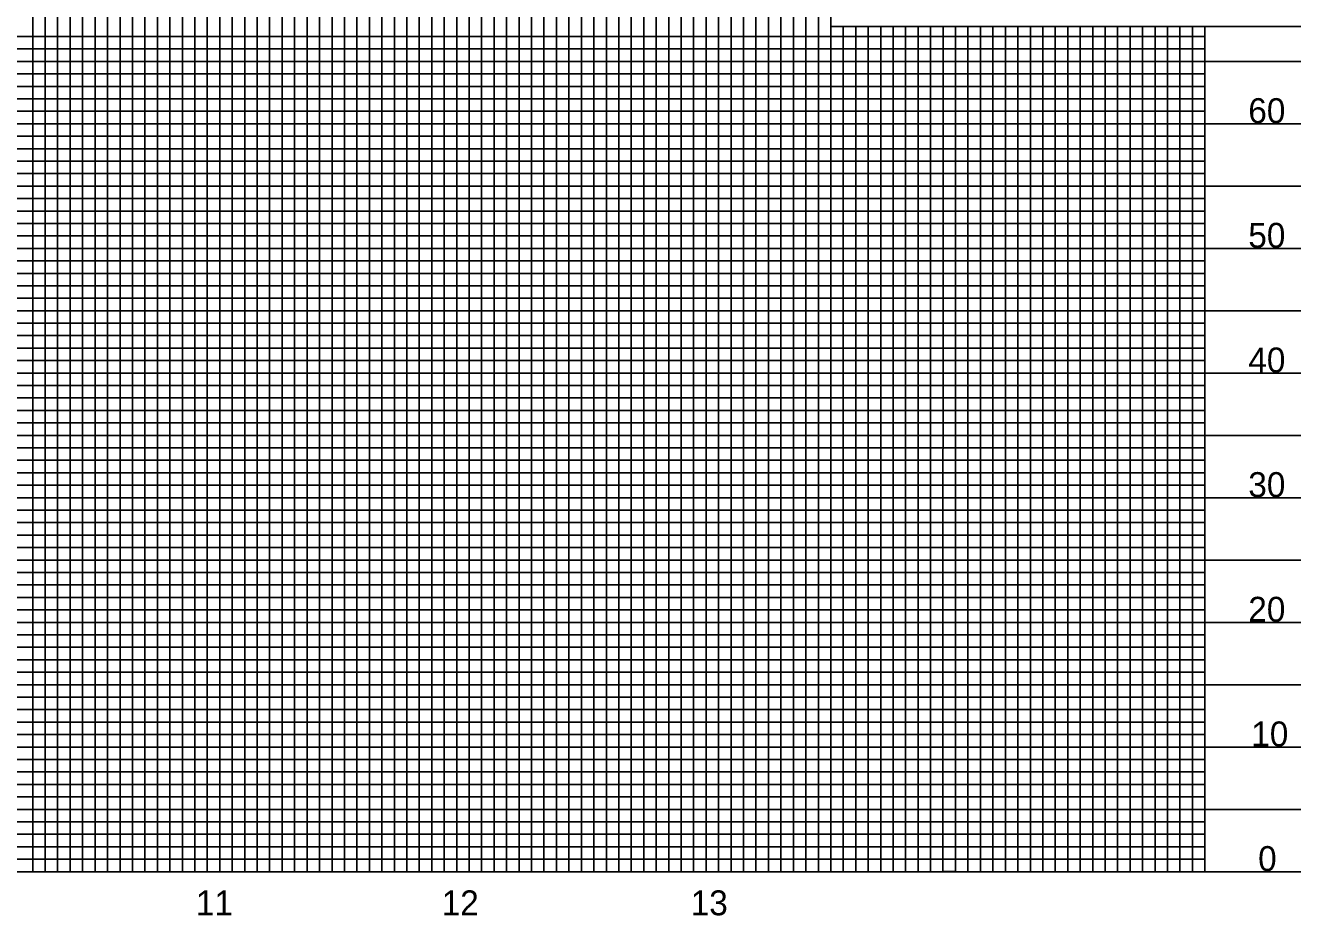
# Model space of a CAD drawing. Extents: x 2186391 to 2188300, y 74582 to 75682.
# Drawn here: x 2187535 to 2188043, y 75140 to 75497 of the extents above; entities that cross this region are included whole.
import ezdxf

# ---------------------------------------------------------------- set-up
doc = ezdxf.new("R2010")
doc.units = 0
for name, color, linetype in [('Old_Level_1', 7, 'Continuous'), ('Old_Level_11', 7, 'Continuous'), ('Old_Level_2', 7, 'Continuous'), ('Old_Level_3', 7, 'Continuous'), ('Sheet Cutting Line CELL', 7, 'Continuous'), ('Sheet Data Field CELL', 7, 'Continuous'), ('Sheet Plot Border Inside CELL', 7, 'Continuous'), ('Sheet Plot Border Outside CELL', 7, 'Continuous'), ('Sheet Sticker Exception Certification CELL', 7, 'Continuous')]:
    doc.layers.add(name, color=color, linetype=linetype)

msp = doc.modelspace()

# ---------------------------------------------------------------- linework, layer by layer
at = {"layer": 'Old_Level_11'}
for p, q in [((2187557.69, 75157.28), (2187557.69, 75657.28)), ((2187607.69, 75157.28), (2187607.69, 75657.28)), ((2187657.69, 75157.28), (2187657.69, 75657.28)), ((2187707.69, 75157.28), (2187707.69, 75657.28)), ((2187757.69, 75157.28), (2187757.69, 75657.28)), ((2187807.69, 75157.28), (2187807.69, 75657.28)), ((2187857.69, 75157.28), (2187857.69, 75519.73)), ((2187907.69, 75157.28), (2187907.69, 75496.23)), ((2187957.69, 75157.28), (2187957.69, 75496.23)), ((2188007.69, 75157.28), (2188007.69, 75496.23)), ((2188057.69, 75457.28), (2186557.69, 75457.28)), ((2188057.69, 75407.28), (2186557.69, 75407.28)), ((2188057.69, 75357.28), (2186557.69, 75357.28)), ((2188057.69, 75307.28), (2186557.69, 75307.28)), ((2188057.69, 75257.28), (2186557.69, 75257.28)), ((2188057.69, 75207.28), (2186557.69, 75207.28))]:
    msp.add_line(p, q, dxfattribs=at)
at = {"layer": 'Old_Level_2'}
for points in [[(2187532.69, 75157.28), (2187582.69, 75157.28), (2187582.69, 75657.28), (2187632.69, 75657.28), (2187632.69, 75157.28), (2187682.69, 75157.28), (2187682.69, 75657.28), (2187732.69, 75657.28), (2187732.69, 75157.28), (2187782.69, 75157.28), (2187782.69, 75657.28), (2187832.69, 75657.28), (2187832.69, 75157.28), (2187882.69, 75157.28), (2187882.69, 75496.23)], [(2187882.69, 75420.08), (2187882.69, 75157.28), (2187932.69, 75157.28), (2187932.69, 75496.23)], [(2187932.69, 75420.08), (2187932.69, 75157.28), (2187982.69, 75157.28), (2187982.69, 75496.23)], [(2188057.69, 75482.28), (2186557.69, 75482.28), (2186557.69, 75432.28), (2187882.69, 75432.28)], [(2187882.69, 75432.28), (2188057.69, 75432.28)], [(2188057.69, 75382.28), (2186557.69, 75382.28), (2186557.69, 75332.28), (2188057.69, 75332.28)], [(2188057.69, 75282.28), (2186557.69, 75282.28), (2186557.69, 75232.28), (2188057.69, 75232.28)], [(2188057.69, 75182.28), (2186557.69, 75182.28)]]:
    msp.add_lwpolyline(points, dxfattribs=at)
at = {"layer": 'Sheet Cutting Line CELL'}
msp.add_line((2186557.69, 75157.28), (2188057.69, 75157.28), dxfattribs=at)
at = {"layer": 'Sheet Data Field CELL'}
for p, q in [((2187857.64, 75496.23), (2187857.64, 75519.73)), ((2187857.64, 75496.23), (2187857.64, 75519.73)), ((2188057.68, 75496.23), (2187857.64, 75496.23)), ((2188057.68, 75496.23), (2187857.64, 75496.23))]:
    msp.add_line(p, q, dxfattribs=at)
at = {"layer": 'Sheet Plot Border Inside CELL'}
msp.add_lwpolyline([(2186607.69, 75496.23), (2186607.69, 75157.28), (2188007.69, 75157.28), (2188007.69, 75496.23)], dxfattribs=at)
at = {"layer": 'Sheet Plot Border Outside CELL'}
for p, q in [((2186607.69, 75492.28), (2188007.69, 75492.28)), ((2188007.69, 75472.28), (2186607.69, 75472.28)), ((2186607.69, 75467.28), (2188007.69, 75467.28)), ((2188007.69, 75447.28), (2186607.69, 75447.28)), ((2186607.69, 75442.28), (2188007.69, 75442.28)), ((2188007.69, 75422.28), (2186607.69, 75422.28)), ((2186607.69, 75417.28), (2188007.69, 75417.28)), ((2188007.69, 75412.28), (2186607.69, 75412.28)), ((2186607.69, 75402.28), (2188007.69, 75402.28)), ((2188007.69, 75397.28), (2186607.69, 75397.28)), ((2186607.69, 75392.28), (2188007.69, 75392.28)), ((2188007.69, 75387.28), (2186607.69, 75387.28)), ((2186607.69, 75377.28), (2188007.69, 75377.28)), ((2188007.69, 75372.28), (2186607.69, 75372.28)), ((2186607.69, 75367.28), (2188007.69, 75367.28)), ((2188007.69, 75362.28), (2186607.69, 75362.28)), ((2186607.69, 75352.28), (2188007.69, 75352.28)), ((2188007.69, 75347.28), (2186607.69, 75347.28)), ((2186607.69, 75342.28), (2188007.69, 75342.28)), ((2188007.69, 75337.28), (2186607.69, 75337.28)), ((2186607.69, 75327.28), (2188007.69, 75327.28)), ((2188007.69, 75322.28), (2186607.69, 75322.28)), ((2186607.69, 75317.28), (2188007.69, 75317.28)), ((2188007.69, 75312.28), (2186607.69, 75312.28)), ((2186607.69, 75302.28), (2188007.69, 75302.28)), ((2188007.69, 75297.28), (2186607.69, 75297.28)), ((2186607.69, 75292.28), (2188007.69, 75292.28)), ((2188007.69, 75287.28), (2186607.69, 75287.28)), ((2186607.69, 75277.28), (2188007.69, 75277.28)), ((2188007.69, 75272.28), (2186607.69, 75272.28)), ((2188007.69, 75267.28), (2186607.69, 75267.28)), ((2188007.69, 75262.28), (2186607.69, 75262.28)), ((2186607.69, 75252.28), (2188007.69, 75252.28)), ((2188007.69, 75247.28), (2186607.69, 75247.28)), ((2186607.69, 75242.28), (2188007.69, 75242.28)), ((2188007.69, 75237.28), (2186607.69, 75237.28)), ((2186607.69, 75227.28), (2188007.69, 75227.28)), ((2188007.69, 75222.28), (2186607.69, 75222.28)), ((2186607.69, 75217.28), (2188007.69, 75217.28)), ((2188007.69, 75212.28), (2186607.69, 75212.28)), ((2186607.69, 75202.28), (2188007.69, 75202.28)), ((2188007.69, 75197.28), (2186607.69, 75197.28)), ((2186607.69, 75192.28), (2188007.69, 75192.28)), ((2188007.69, 75187.28), (2186607.69, 75187.28)), ((2186607.69, 75177.28), (2188007.69, 75177.28)), ((2188007.69, 75172.28), (2186607.69, 75172.28)), ((2186607.69, 75167.28), (2188007.69, 75167.28))]:
    msp.add_line(p, q, dxfattribs=at)
for points in [[(2187537.69, 75657.28), (2187537.69, 75157.28), (2187542.69, 75157.28), (2187542.69, 75657.28)], [(2187547.69, 75657.28), (2187547.69, 75157.28), (2187552.69, 75157.28), (2187552.69, 75657.28)], [(2187562.69, 75657.28), (2187562.69, 75157.28), (2187567.69, 75157.28), (2187567.69, 75657.28)], [(2187572.69, 75657.28), (2187572.69, 75157.28), (2187577.69, 75157.28), (2187577.69, 75657.28)], [(2187587.69, 75657.28), (2187587.69, 75157.28), (2187592.69, 75157.28), (2187592.69, 75657.28)], [(2187597.69, 75657.28), (2187597.69, 75157.28), (2187602.69, 75157.28), (2187602.69, 75657.28)], [(2187612.69, 75657.28), (2187612.69, 75157.28), (2187617.69, 75157.28), (2187617.69, 75657.28)], [(2187622.69, 75657.28), (2187622.69, 75157.28), (2187627.69, 75157.28), (2187627.69, 75657.28)], [(2187637.69, 75657.28), (2187637.69, 75157.28), (2187642.69, 75157.28), (2187642.69, 75657.28)], [(2187647.69, 75657.28), (2187647.69, 75157.28), (2187652.69, 75157.28), (2187652.69, 75657.28)], [(2187662.69, 75657.28), (2187662.69, 75157.28), (2187667.69, 75157.28), (2187667.69, 75657.28)], [(2187672.69, 75657.28), (2187672.69, 75157.28), (2187677.69, 75157.28), (2187677.69, 75657.28)], [(2187687.69, 75657.28), (2187687.69, 75157.28), (2187692.69, 75157.28), (2187692.69, 75657.28)], [(2187697.69, 75657.28), (2187697.69, 75157.28), (2187702.69, 75157.28), (2187702.69, 75657.28)], [(2187712.69, 75657.28), (2187712.69, 75157.28), (2187717.69, 75157.28), (2187717.69, 75657.28)], [(2187722.69, 75657.28), (2187722.69, 75157.28), (2187727.69, 75157.28), (2187727.69, 75657.28)], [(2187737.69, 75657.28), (2187737.69, 75157.28), (2187742.69, 75157.28), (2187742.69, 75657.28)], [(2187747.69, 75657.28), (2187747.69, 75157.28)], [(2187747.69, 75157.28), (2187752.69, 75157.28), (2187752.69, 75657.28)], [(2187762.69, 75657.28), (2187762.69, 75157.28), (2187767.69, 75157.28), (2187767.69, 75657.28)], [(2187772.69, 75657.28), (2187772.69, 75157.28), (2187777.69, 75157.28), (2187777.69, 75657.28)], [(2187787.69, 75657.28), (2187787.69, 75157.28), (2187792.69, 75157.28), (2187792.69, 75657.28)], [(2187797.69, 75657.28), (2187797.69, 75157.28), (2187802.69, 75157.28), (2187802.69, 75657.28)], [(2187812.69, 75657.28), (2187812.69, 75157.28), (2187817.69, 75157.28), (2187817.69, 75657.28)], [(2187822.69, 75657.28), (2187822.69, 75157.28), (2187827.69, 75157.28), (2187827.69, 75657.28)], [(2187837.69, 75657.28), (2187837.69, 75157.28), (2187842.69, 75157.28), (2187842.69, 75657.28)], [(2187847.69, 75657.28), (2187847.69, 75157.28), (2187852.69, 75157.28), (2187852.69, 75657.28)], [(2187862.69, 75496.23), (2187862.69, 75157.28), (2187867.69, 75157.28), (2187867.69, 75496.23)], [(2187872.69, 75496.23), (2187872.69, 75157.28), (2187877.69, 75157.28), (2187877.69, 75496.23)], [(2187887.69, 75496.23), (2187887.69, 75157.28), (2187887.69, 75157.28), (2187892.69, 75157.28), (2187897.69, 75157.28), (2187897.69, 75496.23)], [(2187892.69, 75496.23), (2187892.69, 75157.28)], [(2187902.68, 75496.23), (2187902.59, 75157.33), (2187907.59, 75157.33), (2187912.69, 75157.28), (2187912.69, 75496.23)], [(2187912.69, 75420.08), (2187912.69, 75157.28), (2187917.69, 75157.28), (2187917.69, 75496.23)], [(2187922.69, 75496.23), (2187922.69, 75157.28), (2187927.69, 75157.28), (2187927.69, 75496.23)], [(2187937.69, 75496.23), (2187937.69, 75157.28), (2187942.69, 75157.28), (2187942.69, 75496.23)], [(2187947.69, 75496.23), (2187947.69, 75157.28), (2187952.69, 75157.28), (2187952.69, 75496.23)], [(2187962.69, 75496.23), (2187962.69, 75157.28), (2187967.69, 75157.28), (2187967.69, 75496.23)], [(2187972.69, 75496.23), (2187972.69, 75157.28), (2187977.69, 75157.28), (2187977.69, 75496.23)], [(2187987.69, 75496.23), (2187987.69, 75157.28), (2187992.69, 75157.28), (2187992.69, 75496.23)], [(2187997.69, 75496.23), (2187997.69, 75157.28), (2188002.69, 75157.28), (2188002.69, 75496.23)], [(2188007.69, 75487.28), (2186607.69, 75487.28), (2186607.69, 75477.28), (2188007.69, 75477.28)], [(2188007.69, 75462.28), (2186607.69, 75462.28), (2186607.69, 75452.28), (2188007.69, 75452.28)], [(2188007.69, 75437.28), (2186607.69, 75437.28), (2186607.69, 75427.28), (2188007.69, 75427.28)], [(2188007.69, 75162.28), (2186607.69, 75162.28)]]:
    msp.add_lwpolyline(points, dxfattribs=at)
at = {"layer": 'Sheet Sticker Exception Certification CELL'}
for points in [[(2187507.69, 75157.28), (2187557.69, 75157.28), (2187557.69, 75657.28), (2187607.69, 75657.28), (2187607.69, 75157.28), (2187657.69, 75157.28), (2187657.69, 75657.28), (2187707.69, 75657.28), (2187707.69, 75157.28), (2187757.69, 75157.28), (2187757.69, 75657.28), (2187807.69, 75657.28), (2187807.69, 75157.28), (2187857.69, 75157.28), (2187857.69, 75657.28), (2187883.99, 75657.28)], [(2188007.69, 75496.23), (2188007.69, 75157.28), (2188057.69, 75157.28), (2188057.69, 75507.28)], [(2187907.69, 75496.23), (2187907.69, 75157.28), (2187957.69, 75157.28), (2187957.69, 75157.28), (2187957.69, 75496.23)], [(2188057.69, 75457.28), (2186557.69, 75457.28), (2186557.69, 75407.28), (2188057.69, 75407.28)], [(2188057.69, 75357.28), (2186557.69, 75357.28), (2186557.69, 75307.28), (2188057.69, 75307.28)], [(2188057.69, 75257.28), (2186557.69, 75257.28), (2186557.69, 75257.28), (2186557.69, 75207.28), (2188057.69, 75207.28)]]:
    msp.add_lwpolyline(points, dxfattribs=at)

# ---------------------------------------------------------------- texts
at = {"layer": 'Old_Level_1'}
for s, p in [('11', (2187603.11, 75139.78)), ('12', (2187701.66, 75139.78)), ('13', (2187801.5, 75139.78))]:
    msp.add_text(s, height=10, dxfattribs=at).set_placement(p)
at = {"layer": 'Old_Level_3'}
for s, p in [('60', (2188025.08, 75457.53)), ('50', (2188025.08, 75407.53)), ('40', (2188025.08, 75357.53)), ('30', (2188025.08, 75307.53)), ('20', (2188025.08, 75257.53)), ('10', (2188026.27, 75207.53)), ('0', (2188029.03, 75157.53))]:
    msp.add_text(s, height=10, dxfattribs=at).set_placement(p)

doc.saveas('drawing.dxf')
